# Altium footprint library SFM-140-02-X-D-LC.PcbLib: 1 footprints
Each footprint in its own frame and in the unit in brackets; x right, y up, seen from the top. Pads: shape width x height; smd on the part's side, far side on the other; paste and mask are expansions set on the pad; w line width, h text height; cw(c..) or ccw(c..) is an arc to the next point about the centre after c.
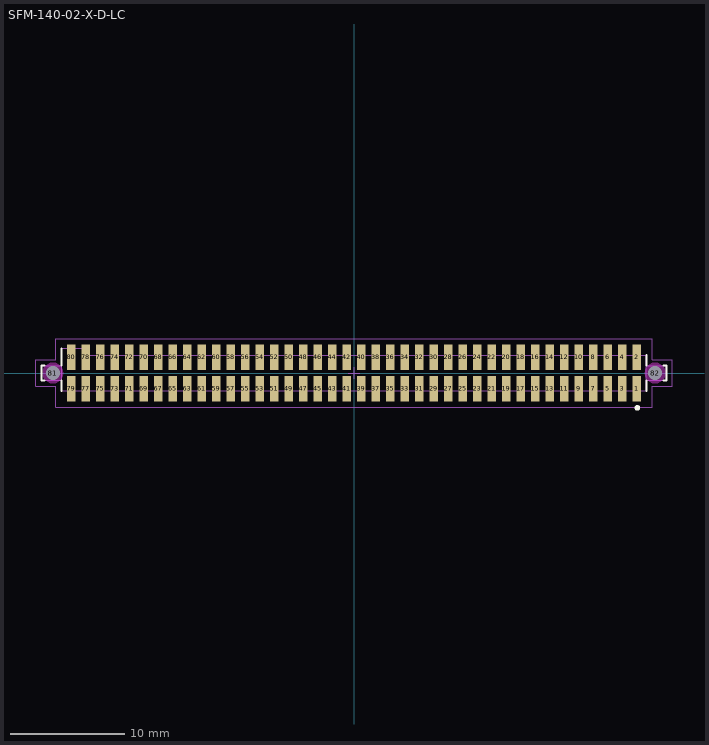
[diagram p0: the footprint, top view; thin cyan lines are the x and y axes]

## SFM-140-02-X-D-LC [mm] "1.27mm pitch, 80 pin, socket strip; w/locking clips, SMT"
height 4.57
pads (82):
  rect 0.75x2.25 smd mask+0: 1(24.765,-1.375) 2(24.765,1.375) 3(23.495,-1.375) 4(23.495,1.375) 5(22.225,-1.375) 6(22.225,1.375) 7(20.955,-1.375) 8(20.955,1.375) 9(19.685,-1.375) 10(19.685,1.375) 11(18.415,-1.375) 12(18.415,1.375) 13(17.145,-1.375) 14(17.145,1.375) 15(15.875,-1.375) 16(15.875,1.375) 17(14.605,-1.375) 18(14.605,1.375) 19(13.335,-1.375) 20(13.335,1.375) 21(12.065,-1.375) 22(12.065,1.375) 23(10.795,-1.375) 24(10.795,1.375) 25(9.525,-1.375) 26(9.525,1.375) 27(8.255,-1.375) 28(8.255,1.375) 29(6.985,-1.375) 30(6.985,1.375) 31(5.715,-1.375) 32(5.715,1.375) 33(4.445,-1.375) 34(4.445,1.375) 35(3.175,-1.375) 36(3.175,1.375) 37(1.905,-1.375) 38(1.905,1.375) 39(0.635,-1.375) 40(0.635,1.375) 41(-0.635,-1.375) 42(-0.635,1.375) 43(-1.905,-1.375) 44(-1.905,1.375) 45(-3.175,-1.375) 46(-3.175,1.375) 47(-4.445,-1.375) 48(-4.445,1.375) 49(-5.715,-1.375) 50(-5.715,1.375) 51(-6.985,-1.375) 52(-6.985,1.375) 53(-8.255,-1.375) 54(-8.255,1.375) 55(-9.525,-1.375) 56(-9.525,1.375) 57(-10.795,-1.375) 58(-10.795,1.375) 59(-12.065,-1.375) 60(-12.065,1.375) 61(-13.335,-1.375) 62(-13.335,1.375) 63(-14.605,-1.375) 64(-14.605,1.375) 65(-15.875,-1.375) 66(-15.875,1.375) 67(-17.145,-1.375) 68(-17.145,1.375) 69(-18.415,-1.375) 70(-18.415,1.375) 71(-19.685,-1.375) 72(-19.685,1.375) 73(-20.955,-1.375) 74(-20.955,1.375) 75(-22.225,-1.375) 76(-22.225,1.375) 77(-23.495,-1.375) 78(-23.495,1.375) 79(-24.765,-1.375) 80(-24.765,1.375)
  round 1 hole 1.2 unplated mask+0: 81(-26.352,0) 82(26.352,0)
Top Overlay:
  circle w0.25: c24.8,-3.05 r0.125
  lines w0.2: -27.1,-0.65 -27.35,-0.65 -27.35,0.65 -27.1,0.65 ; -25.6,-1.55 -25.6,-0.65 ; -25.6,0.65 -25.6,2.15 ; 25.6,-1.55 25.6,-0.65 ; 25.6,0.65 25.6,1.55 ; 27.1,-0.65 27.35,-0.65 27.35,0.65 27.1,0.65
Keep-Out Layer:
  pour cut-out: -25.445,0 -25.476,0.235 -25.567,0.454 -25.711,0.642 -25.899,0.786 -26.118,0.877 -26.353,0.908 -26.588,0.877 -26.807,0.786 -26.995,0.642 -27.139,0.454 -27.23,0.235 -27.26,0 -27.23,-0.235 -27.139,-0.454 -26.995,-0.642 -26.807,-0.786 -26.588,-0.877 -26.353,-0.908 -26.118,-0.877 -25.899,-0.786 -25.711,-0.642 -25.567,-0.454 -25.476,-0.235
  pour cut-out: 27.258,0 27.227,0.235 27.136,0.454 26.992,0.642 26.804,0.786 26.585,0.877 26.35,0.908 26.115,0.877 25.896,0.786 25.708,0.642 25.564,0.454 25.473,0.235 25.442,0 25.473,-0.235 25.564,-0.454 25.708,-0.642 25.896,-0.786 26.115,-0.877 26.35,-0.908 26.585,-0.877 26.804,-0.786 26.992,-0.642 27.136,-0.454 27.227,-0.235
Mechanical 12:
  lines w0.001: -27.35,-0.65 -27.35,0.65 -25.6,0.65 -25.6,2.15 -23.55,2.15 -23.55,1.55 25.6,1.55 25.6,0.65 27.35,0.65 27.35,-0.65 25.6,-0.65 25.6,-1.55 -25.6,-1.55 -25.6,-0.65 -27.35,-0.65
Mechanical 13:
  lines w0.1: -25.6,-0.65 -25.6,0.65 ; -25.6,-0.65 -27.35,-0.65 -27.35,0.65 -25.6,0.65 ; -25.6,-0.65 -25.6,-1.55 25.6,-1.55 25.6,-0.65 ; -25.6,0.65 -25.6,2.15 -23.55,2.15 -23.55,1.55 25.6,1.55 25.6,0.65 ; 25.6,-0.65 27.35,-0.65 27.35,0.65 25.6,0.65 ; 25.6,-0.65 25.6,0.65
  text ".Designator" at 0,-0.127 h1.52
Mechanical 15:
  lines w0.05: -0.5,0 0.5,0 ; 0,-0.5 0,0.5 ; -27.85,-1.15 -26.1,-1.15 -26.1,-3 26.1,-3 26.1,-1.15 27.85,-1.15 27.85,1.15 26.1,1.15 26.1,3 -26.1,3 -26.1,1.15 -27.85,1.15 -27.85,-1.15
